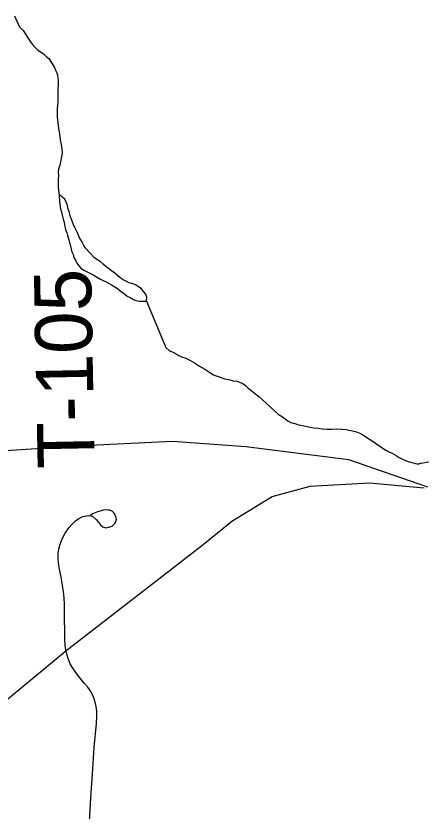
# Model space of a CAD drawing. Extents: x 103424 to 286016, y 38711 to 110967.
# Drawn here: x 119767 to 121934, y 71273 to 75475 of the extents above; entities that cross this region are included whole.
import ezdxf

# ---------------------------------------------------------------- set-up
doc = ezdxf.new("R2010")
doc.units = 0
for name, color, linetype in [('GM_X_Minor_Lake', 7, 'Continuous'), ('GM_X_Minor_River', 7, 'Continuous'), ('GM_X_Rail_Line', 7, 'Continuous'), ('GM_X_Township_Road', 7, 'Continuous'), ('GM_X_Township_Road_Text', 7, 'Continuous')]:
    doc.layers.add(name, color=color, linetype=linetype)

msp = doc.modelspace()

# ---------------------------------------------------------------- linework, layer by layer
at = {"layer": 'GM_X_Minor_Lake'}
for points in [[(119997.2, 74531.5), (119996.7, 74526), (119996.9, 74489.7), (120001.1, 74471.6), (120003.2, 74453.5), (120007.3, 74439.4), (120011.5, 74421.3), (120015.6, 74407.2), (120019.7, 74389.1), (120023.9, 74375), (120026, 74360.9), (120030.1, 74346.8), (120036.3, 74328.7), (120040.4, 74314.6), (120044.5, 74296.5), (120050.7, 74278.4), (120059, 74242.1), (120063.1, 74228.1), (120069.2, 74214), (120073.4, 74197.9), (120081.5, 74183.8), (120089.7, 74167.8), (120099.8, 74153.7), (120112, 74139.7), (120130.2, 74129.7), (120146.4, 74119.8), (120160.5, 74113.8), (120178.7, 74103.8), (120192.8, 74095.9), (120211, 74085.9), (120225.1, 74078), (120243.3, 74070), (120271.6, 74054.1), (120289.8, 74042.1), (120304, 74034.1), (120318.1, 74022.1), (120340.4, 74006.2), (120354.5, 73994.2), (120370.7, 73986.2), (120388.9, 73976.2), (120403, 73970.3), (120419.1, 73966.4), (120456.9, 73966.6)], [(120182.8, 74196.3), (120135.4, 74246.7), (120125.3, 74260.7), (120119.1, 74274.8), (120111, 74290.9), (120100.8, 74304.9), (120094.6, 74325.1), (120078.3, 74357.2), (120070.1, 74375.3), (120064, 74389.4), (120059.9, 74403.5), (120053.8, 74417.5), (120049.6, 74435.6), (120043.4, 74453.7), (120039.3, 74471.9), (120033.1, 74490), (120025, 74506), (120008.8, 74520), (119997.2, 74531.5)], [(120456.9, 73966.6), (120459.2, 73988.8), (120453.1, 74004.9), (120440.9, 74018.9), (120428.7, 74035), (120414.6, 74042.9), (120398.4, 74052.9), (120380.3, 74060.9), (120366.1, 74064.8), (120348, 74072.7), (120333.8, 74080.7), (120317.6, 74090.7), (120303.5, 74102.7), (120289.3, 74114.7), (120273.1, 74126.7), (120256.9, 74140.7), (120242.8, 74150.7), (120228.6, 74162.7), (120212.4, 74176.7), (120194.2, 74186.6), (120182.8, 74196.3)]]:
    msp.add_lwpolyline(points, dxfattribs=at)
at = {"layer": 'GM_X_Minor_River'}
for points in [[(119759.6, 75474.7), (119772.1, 75446.5), (119786.6, 75416.4), (119804.9, 75398.4), (119817.3, 75378.3), (119829.6, 75358.2), (119842, 75340.2), (119854.3, 75324.1), (119868.6, 75308.1), (119882.9, 75294.1), (119901.2, 75282.2), (119915.5, 75272.2), (119927.7, 75260.2), (119942, 75250.2), (119970.8, 75202.1), (119977, 75188), (119983.3, 75173.9), (119987.4, 75161.8), (119989.6, 75147.7), (119989.8, 75131.5), (119990, 75111.4), (119988.3, 75085.1), (119988.6, 75060.8)], [(119988.6, 75060.8), (119988.9, 75038.6), (119989.1, 75020.4), (119987.3, 75002.2), (119985.5, 74984), (119985.7, 74963.8), (119986, 74939.6), (119988.3, 74911.4), (119992.7, 74879.1), (119997.1, 74850.8), (120001.5, 74820.6), (120005.8, 74794.4), (120010.1, 74770.2), (120012.4, 74752), (120010.5, 74737.9), (120006.7, 74721.7), (120002.8, 74703.4), (119999, 74685.2), (119993.2, 74665), (119991.4, 74648.8), (119991.5, 74632.6), (119989.8, 74608.4), (119990.1, 74584.1), (119990.3, 74570), (119996.7, 74526)], [(120456.9, 73966.6), (120559.5, 73723.2), (120577.9, 73705.2), (120590.1, 73701.3), (120604.3, 73693.4), (120620.6, 73683.4), (120642.9, 73673.5), (120665.2, 73665.7), (120685.5, 73655.8), (120709.9, 73641.9), (120736.4, 73624), (120764.8, 73608.1), (120791.3, 73590.2), (120811.6, 73578.3), (120825.8, 73572.4), (120838, 73568.4), (120850.2, 73564.5), (120870.5, 73556.6), (120892.7, 73552.8), (120915, 73547), (120935.2, 73545.2), (120965.7, 73531.3), (120979.9, 73521.4), (120994.2, 73507.4), (121016.6, 73489.4), (121035, 73475.5), (121051.3, 73463.5), (121067.6, 73447.5), (121090.1, 73427.5), (121110.5, 73409.6), (121130.9, 73389.5), (121153.4, 73369.6), (121175.7, 73355.7), (121190, 73345.7), (121204.2, 73335.7), (121220.5, 73325.8), (121240.8, 73319.9), (121257, 73316.1), (121279.3, 73310.2), (121299.5, 73306.4), (121319.8, 73300.5), (121342, 73298.7), (121364.2, 73296.9), (121386.5, 73293.1), (121410.8, 73291.3), (121435, 73291.6), (121461.3, 73291.8), (121491.6, 73290.1), (121511.8, 73288.3), (121525.9, 73286.4), (121546.2, 73282.6), (121566.4, 73276.7), (121584.7, 73268.8), (121603, 73258.9), (121621.3, 73247), (121639.7, 73235), (121653.9, 73225.1), (121666.1, 73217.1), (121684.4, 73205.2), (121694.6, 73197.2), (121706.8, 73189.2), (121721.1, 73179.3), (121737.3, 73171.4), (121751.5, 73165.4), (121763.7, 73159.5), (121775.9, 73151.6), (121792.2, 73141.6), (121806.4, 73133.7), (121822.7, 73127.8), (121845, 73117.9), (121885.5, 73108.2), (121895.6, 73108.3), (121905.7, 73110.4), (121917.8, 73112.6), (121933.9, 73116.8), (121948, 73118.9)]]:
    msp.add_lwpolyline(points, dxfattribs=at)
at = {"layer": 'GM_X_Rail_Line'}
for points in [[(121943.9, 72984.2), (121526.3, 73129.4), (120981.6, 73197.1), (120593.9, 73224.9), (120086.2, 73200.2), (119529.3, 73163.3), (118649.2, 73123.3), (117926.1, 73095.6), (116901.4, 73111), (115701.4, 73092.5)], [(118653.8, 71253.5), (118905.6, 71333.1), (119226.8, 71499.5), (119680.1, 71830.2), (120031.4, 72118.7), (120756.4, 72682.1), (120907.7, 72805.4), (121120.6, 72934.3), (121322.4, 72990.3), (121635.7, 73006.6), (121924.3, 72981.4)]]:
    msp.add_lwpolyline(points, dxfattribs=at)
at = {"layer": 'GM_X_Township_Road'}
msp.add_lwpolyline([(120155.8, 71217.2), (120163.9, 71343), (120172, 71468.8), (120181, 71608), (120192.6, 71734.8), (120195.3, 71775.1), (120194.7, 71801.3), (120191.3, 71824.9), (120185.4, 71848.2), (120178.5, 71871.4), (120168.9, 71893.2), (120159, 71909.6), (120147, 71926.8), (120128.6, 71948.9), (120092.2, 71993.4), (120076.7, 72014.9), (120064.6, 72033.8), (120054.5, 72051.3), (120044.4, 72074.3), (120035.6, 72101.2), (120031.6, 72124.8), (120028.2, 72149), (120026.2, 72181.4), (120024.9, 72330.3), (120024.2, 72364), (120021.5, 72399), (120018.9, 72432), (120014.1, 72465.8), (120006.7, 72508.2), (119996.5, 72560.1), (119992.5, 72583.7), (119990.5, 72609.3), (119991.2, 72635.5), (119993.9, 72657.1), (120000.6, 72683.4), (120012.1, 72711.3), (120027.2, 72741.1), (120046.4, 72769.4), (120064.1, 72789.6), (120082.3, 72806.3), (120100.5, 72818.4), (120120.4, 72829.1), (120148.9, 72835.4), (120172.6, 72830.4), (120191.3, 72813.1), (120204.2, 72800.2), (120214.3, 72785.1), (120227.2, 72775), (120242.4, 72770), (120258.2, 72772.1), (120276.2, 72778.6), (120289.8, 72791.5), (120295.6, 72804.5), (120298.4, 72817.4), (120295.6, 72827.5), (120290.5, 72841.1), (120285.5, 72849.1), (120275.4, 72857), (120263.2, 72862), (120255.3, 72862.7), (120245.2, 72864.2), (120230.1, 72863.5), (120198.5, 72854.8), (120172.6, 72844), (120161.1, 72835.4)], dxfattribs=at)

# ---------------------------------------------------------------- texts
at = {"layer": 'GM_X_Township_Road_Text'}
msp.add_text('T-105', height=301.87, rotation=91.1227, dxfattribs=at).set_placement((120184.3, 73085.9))

doc.saveas('drawing.dxf')
